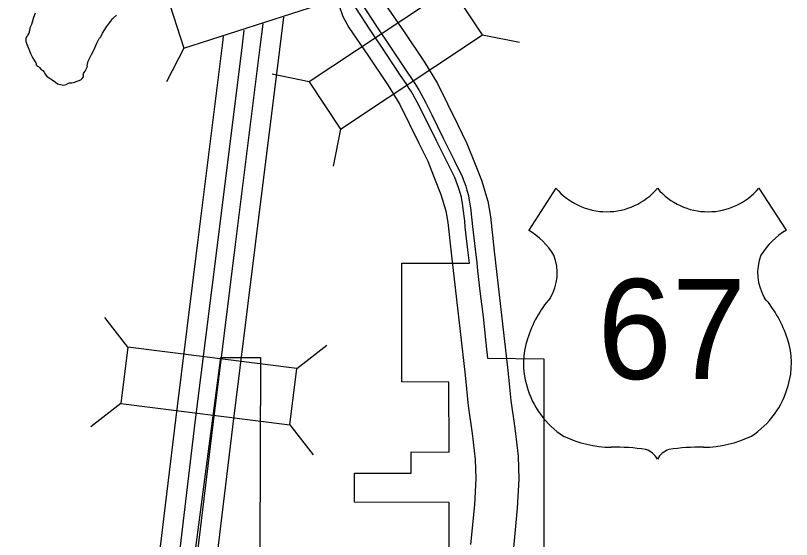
# Model space of a CAD drawing. Extents: x 1373862 to 1377080, y 1164775 to 1170415.
# Drawn here: x 1374285.5 to 1374339.7, y 1169899.9 to 1169936.4 of the extents above; entities that cross this region are included whole.
import ezdxf

# ---------------------------------------------------------------- set-up
doc = ezdxf.new("R2010")
doc.units = 0
doc.layers.add('Default', color=7, linetype='Continuous')

msp = doc.modelspace()

# ---------------------------------------------------------------- linework, layer by layer
at = {"layer": 'Default'}
for p, q in [((1374318.129, 1169935.068), (1374320.717, 1169934.545)), ((1374297.292, 1169934.136), (1374296.089, 1169931.786)), ((1374306.041, 1169931.798), (1374303.453, 1169932.321)), ((1374308.231, 1169928.499), (1374307.708, 1169925.911)), ((1374323.25, 1169924.384), (1374321.347, 1169921.44)), ((1374337.406, 1169924.384), (1374339.31, 1169921.44)), ((1374293.391, 1169913.288), (1374291.771, 1169915.373)), ((1374305.179, 1169911.813), (1374307.263, 1169913.433)), ((1374292.899, 1169909.359), (1374290.815, 1169907.739)), ((1374304.687, 1169907.883), (1374306.307, 1169905.799))]:
    msp.add_line(p, q, dxfattribs=at)
for points in [[(1374307.381, 1169941.553), (1374296.076, 1169937.904), (1374297.292, 1169934.136), (1374308.598, 1169937.785)], [(1374308.231, 1169928.499), (1374318.129, 1169935.068), (1374315.94, 1169938.367), (1374306.041, 1169931.798)], [(1374305.179, 1169911.813), (1374293.391, 1169913.288), (1374292.899, 1169909.359), (1374304.687, 1169907.883)]]:
    msp.add_lwpolyline(points, close=True, dxfattribs=at)
for points in [[(1374307.502, 1169938.183), (1374308.11, 1169937.159), (1374308.387, 1169936.348), (1374308.802, 1169935.575)], [(1374315.807, 1169899.11), (1374315.801, 1169902.469), (1374309.206, 1169902.482), (1374309.207, 1169904.51), (1374313.154, 1169904.502), (1374313.155, 1169905.992), (1374315.795, 1169905.987), (1374315.786, 1169910.865), (1374312.498, 1169910.871), (1374312.497, 1169912.55), (1374312.492, 1169919.153), (1374315.771, 1169919.161), (1374317.219, 1169919.145), (1374317.108, 1169920.075), (1374316.925, 1169921.65), (1374316.886, 1169922.097), (1374316.786, 1169922.933), (1374316.728, 1169923.323), (1374316.69, 1169923.56), (1374316.65, 1169923.743), (1374316.482, 1169924.357), (1374316.284, 1169924.862), (1374316.186, 1169925.117), (1374316.103, 1169925.298), (1374315.7, 1169926.102), (1374314.939, 1169927.638), (1374314.132, 1169929.286), (1374314.045, 1169929.452), (1374313.729, 1169930.081), (1374313.267, 1169930.938), (1374313.175, 1169931.09), (1374313.021, 1169931.328), (1374312.808, 1169931.674), (1374312.416, 1169932.242), (1374311.34, 1169933.848), (1374310.298, 1169935.423), (1374309.28, 1169936.942)], [(1374309.698, 1169937.222), (1374310.717, 1169935.702), (1374311.759, 1169934.127), (1374312.832, 1169932.525), (1374313.229, 1169931.949), (1374313.447, 1169931.596), (1374313.704, 1169931.189), (1374313.821, 1169930.97), (1374314.176, 1169930.314), (1374314.493, 1169929.681), (1374314.59, 1169929.495), (1374315.389, 1169927.862), (1374316.15, 1169926.326), (1374316.556, 1169925.516), (1374316.65, 1169925.312), (1374316.838, 1169924.826), (1374316.96, 1169924.516), (1374317.039, 1169924.229), (1374317.139, 1169923.863), (1374317.184, 1169923.653), (1374317.225, 1169923.4), (1374317.284, 1169923), (1374317.386, 1169922.149), (1374317.426, 1169921.701), (1374317.608, 1169920.133), (1374317.722, 1169919.173), (1374317.788, 1169918.62), (1374317.971, 1169917.018), (1374318.045, 1169916.314), (1374318.163, 1169915.409), (1374318.366, 1169913.593), (1374318.411, 1169913.148), (1374318.482, 1169912.518), (1374322.407, 1169912.479), (1374322.398, 1169899.089)], [(1374311.364, 1169937.146), (1374312.664, 1169935.273), (1374314.073, 1169933.15), (1374314.987, 1169931.663), (1374316.387, 1169928.83), (1374317.045, 1169927.487), (1374317.621, 1169926.049), (1374318.064, 1169924.924), (1374318.502, 1169923.469), (1374318.682, 1169922.393), (1374318.939, 1169919.995), (1374319.887, 1169911.673), (1374320.114, 1169909.571), (1374320.376, 1169907.656), (1374320.62, 1169905.7), (1374320.67, 1169904.091), (1374320.55, 1169902.073), (1374320.291, 1169899.31)], [(1374286.928, 1169936.583), (1374286.815, 1169936.28), (1374286.656, 1169935.795), (1374286.552, 1169935.542), (1374286.521, 1169935.343), (1374286.471, 1169935.189), (1374286.417, 1169935.066), (1374286.376, 1169934.998), (1374286.308, 1169934.926), (1374286.272, 1169934.813), (1374286.276, 1169934.605), (1374286.317, 1169934.491), (1374286.349, 1169934.365), (1374286.394, 1169934.292), (1374286.507, 1169934.016), (1374286.584, 1169933.767), (1374286.765, 1169933.45), (1374286.978, 1169933.12), (1374286.991, 1169933.043), (1374286.996, 1169932.979), (1374287.027, 1169932.929), (1374287.095, 1169932.871), (1374287.154, 1169932.852), (1374287.222, 1169932.794), (1374287.322, 1169932.667), (1374287.448, 1169932.576), (1374287.557, 1169932.454), (1374287.652, 1169932.309), (1374287.742, 1169932.155), (1374287.783, 1169932.128), (1374287.887, 1169932.069), (1374288.1, 1169931.933), (1374288.33, 1169931.761), (1374288.489, 1169931.644), (1374288.561, 1169931.616), (1374288.688, 1169931.612), (1374288.81, 1169931.571), (1374288.9, 1169931.562), (1374289, 1169931.576), (1374289.09, 1169931.598), (1374289.249, 1169931.698), (1374289.308, 1169931.712), (1374289.475, 1169931.725), (1374289.602, 1169931.748), (1374289.923, 1169931.861), (1374290.099, 1169931.929), (1374290.176, 1169931.992), (1374290.285, 1169932.142), (1374290.303, 1169932.223), (1374290.303, 1169932.268), (1374290.28, 1169932.291), (1374290.271, 1169932.327), (1374290.285, 1169932.377), (1374290.344, 1169932.445), (1374290.402, 1169932.531), (1374290.561, 1169932.861)], [(1374290.561, 1169932.861), (1374290.551, 1169932.875), (1374290.543, 1169932.889), (1374290.556, 1169932.938), (1374290.62, 1169933.224), (1374290.665, 1169933.328), (1374290.85, 1169933.686), (1374291.022, 1169933.989), (1374291.217, 1169934.491), (1374291.316, 1169934.668), (1374291.384, 1169934.804), (1374291.506, 1169934.926), (1374291.624, 1169935.175), (1374291.891, 1169935.623), (1374292.04, 1169935.8), (1374292.19, 1169936.013), (1374292.298, 1169936.189), (1374292.357, 1169936.234), (1374292.597, 1169936.438)], [(1374296.336, 1169886.48), (1374296.491, 1169887.013), (1374296.948, 1169889.296), (1374297.379, 1169892.188), (1374298.178, 1169898.298), (1374299.333, 1169907.903), (1374300.903, 1169920.445), (1374302.622, 1169934.213), (1374302.823, 1169935.829)], [(1374297.661, 1169886.112), (1374297.828, 1169886.685), (1374298.303, 1169889.059), (1374298.741, 1169891.997), (1374299.543, 1169898.127), (1374300.698, 1169907.735), (1374302.268, 1169920.274), (1374303.986, 1169934.043), (1374304.266, 1169936.288)], [(1374295.123, 1169886.787), (1374295.276, 1169887.311), (1374295.717, 1169889.511), (1374296.141, 1169892.361), (1374296.938, 1169898.454), (1374298.092, 1169908.055), (1374299.663, 1169920.6), (1374301.381, 1169934.368), (1374301.509, 1169935.389)], [(1374308.802, 1169935.575), (1374310.182, 1169933.588), (1374311.545, 1169931.535), (1374312.359, 1169930.21), (1374313.695, 1169927.505), (1374314.302, 1169926.267), (1374314.833, 1169924.942), (1374315.227, 1169923.94), (1374315.575, 1169922.786), (1374315.709, 1169921.986), (1374315.957, 1169919.666), (1374316.906, 1169911.342), (1374317.135, 1169909.207), (1374317.402, 1169907.267), (1374317.625, 1169905.467), (1374317.668, 1169904.133), (1374317.558, 1169902.303), (1374317.298, 1169899.529)], [(1374293.814, 1169887.208), (1374293.94, 1169887.639), (1374294.362, 1169889.747), (1374294.779, 1169892.551), (1374295.574, 1169898.625), (1374296.728, 1169908.222), (1374298.299, 1169920.771), (1374300.017, 1169934.538), (1374300.068, 1169934.95)], [(1374282.827, 1169872.63), (1374287.773, 1169872.591), (1374288.754, 1169874.779), (1374290.932, 1169874.787), (1374289.999, 1169872.575), (1374291.092, 1169872.587), (1374291.714, 1169874.14), (1374292.496, 1169875.928), (1374293.677, 1169878.914), (1374294.682, 1169881.645), (1374295.4, 1169884.407), (1374295.77, 1169885.881), (1374295.964, 1169885.881), (1374296.222, 1169886.846), (1374296.449, 1169887.82), (1374296.939, 1169890.764), (1374297.254, 1169892.516), (1374298.109, 1169899.148), (1374299.861, 1169912.572), (1374302.64, 1169912.567), (1374302.602, 1169899.138), (1374303.702, 1169899.136), (1374303.686, 1169892.513), (1374302.586, 1169892.514)]]:
    msp.add_lwpolyline(points, dxfattribs=at)
for centre, radius, start, end in [((1374326.796, 1169927.367), 4.634, 220.075, 319.6701), ((1374333.861, 1169927.367), 4.634, 220.3299, 319.925), ((1374318.859, 1169917.165), 4.946, 30.7809, 59.9883), ((1374341.798, 1169917.165), 4.946, 120.0117, 149.2191), ((1374319.947, 1169918.47), 3.391, 328.8105, 21.2108), ((1374340.71, 1169918.47), 3.391, 158.7892, 211.1895), ((1374328.814, 1169911.519), 7.911, 138.9565, 162.6913), ((1374331.842, 1169911.519), 7.911, 17.3087, 41.0435), ((1374326.203, 1169912.168), 5.227, 160.9576, 197.3819), ((1374334.454, 1169912.168), 5.227, 342.6181, 19.0424), ((1374327.054, 1169912.182), 6.048, 195.1074, 237.1312), ((1374333.603, 1169912.182), 6.048, 302.8688, 344.8926), ((1374327.166, 1169914.087), 7.767, 244.0771, 269.5779), ((1374333.49, 1169914.087), 7.767, 270.4221, 295.9229), ((1374327.346, 1169892.097), 14.227, 81.1942, 90.9539), ((1374329.125, 1169904.852), 1.363, 28.0342, 72.9864), ((1374331.532, 1169904.852), 1.363, 107.0136, 151.9658), ((1374333.311, 1169892.097), 14.227, 89.0461, 98.8058)]:
    msp.add_arc(centre, radius, start, end, dxfattribs=at)

# ---------------------------------------------------------------- texts
msp.add_text('67', height=6.9696, dxfattribs=at).set_placement((1374326.148, 1169911.079))

doc.saveas('drawing.dxf')
